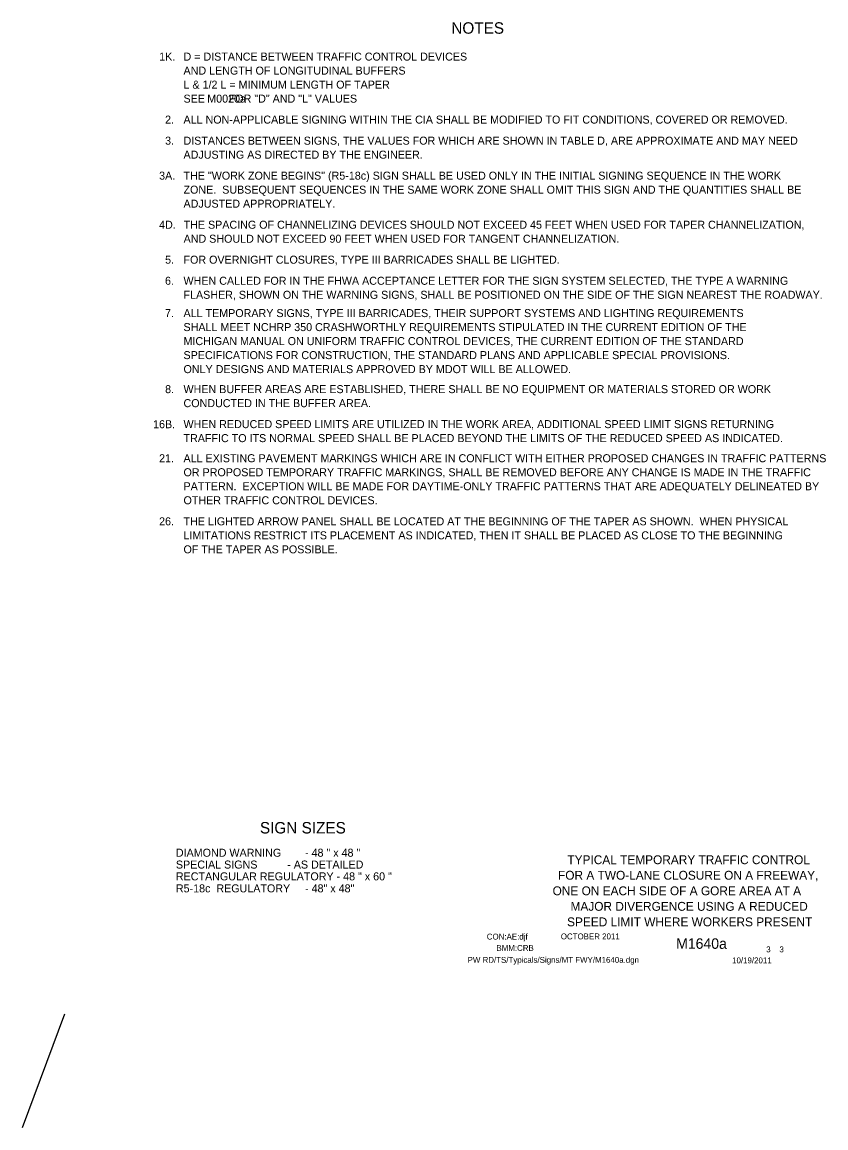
# Model space of a CAD drawing. Extents: x 16512 to 19504, y 5761 to 6984.
# Drawn here: x 18661 to 19504, y 5761 to 6921 of the extents above; entities that cross this region are included whole.
import ezdxf

# ---------------------------------------------------------------- set-up
doc = ezdxf.new("R2010")
doc.units = 0
for name, color, linetype in [('BORDER', 7, 'Continuous'), ('BORDER_SIGNAL_WO', 7, 'Continuous'), ('TYPICAL_TEXT_DIMEN_PR', 7, 'Continuous')]:
    doc.layers.add(name, color=color, linetype=linetype)

msp = doc.modelspace()

# ---------------------------------------------------------------- linework, layer by layer
at = {"layer": 'TYPICAL_TEXT_DIMEN_PR'}
msp.add_line((18705.8, 5880), (18661.5, 5760.5), dxfattribs=at)

# ---------------------------------------------------------------- texts
at = {"layer": 'BORDER'}
for s, p in [('TYPICAL TEMPORARY TRAFFIC CONTROL', (19233.2, 6037.2)), ('FOR A TWO-LANE CLOSURE ON A FREEWAY,', (19223.4, 6020.9)), ('ONE ON EACH SIDE OF A GORE AREA AT A ', (19217.7, 6004.6)), ('MAJOR DIVERGENCE USING A REDUCED', (19236.5, 5988.3)), ('SPEED LIMIT WHERE WORKERS PRESENT', (19232.9, 5972))]:
    msp.add_text(s, height=9.3, dxfattribs=at).set_placement(p)
at = {"layer": 'BORDER_SIGNAL_WO'}
for s, height, p in [('CON:AE:djf  ', 6.2, (19148.7, 5958.1)), ('    OCTOBER 2011    ', 6.2, (19217.1, 5958.3)), ('BMM:CRB   ', 6.2, (19158.8, 5946.2)), ('    M1640a   ', 11, (19330.9, 5948.4)), ('PW RD/TS/Typicals/Signs/MT FWY/M1640a.dgn      ', 6.2, (19128.6, 5933.7)), (' 3    3 ', 6.2, (19439.4, 5944.7)), ('10/19/2011    ', 6.2, (19405.9, 5933.1))]:
    msp.add_text(s, height=height, dxfattribs=at).set_placement(p)
at = {"layer": 'TYPICAL_TEXT_DIMEN_PR'}
for s, height, p in [('NOTES', 12, (19111.5, 6908.5)), ('1K.', 8.4, (18805.2, 6880.3)), ('D = DISTANCE BETWEEN TRAFFIC CONTROL DEVICES', 8.4, (18830.7, 6880.3)), ('AND LENGTH OF LONGITUDINAL BUFFERS', 8.4, (18830.7, 6865.6)), ('L & 1/2 L = MINIMUM LENGTH OF TAPER', 8.4, (18830.7, 6850.9)), ('SEE        FOR "D" AND "L" VALUES', 8.4, (18830.7, 6836.2)), ('M0020a', 8.4, (18855.6, 6836.2)), ('2.', 8.4, (18811.4, 6814.2)), ('ALL NON-APPLICABLE SIGNING WITHIN THE CIA SHALL BE MODIFIED TO FIT CONDITIONS, COVERED OR REMOVED.', 8.4, (18830.7, 6814.2)), ('3.', 8.4, (18811.4, 6792.1)), ('DISTANCES BETWEEN SIGNS, THE VALUES FOR WHICH ARE SHOWN IN TABLE D, ARE APPROXIMATE AND MAY NEED', 8.4, (18830.7, 6792.1)), ('ADJUSTING AS DIRECTED BY THE ENGINEER.', 8.4, (18830.7, 6777.4)), ('3A.', 8.4, (18805.1, 6755.4)), ('THE "WORK ZONE BEGINS" (R5-18c) SIGN SHALL BE USED ONLY IN THE INITIAL SIGNING SEQUENCE IN THE WORK', 8.4, (18830.7, 6755.4)), ('ZONE.  SUBSEQUENT SEQUENCES IN THE SAME WORK ZONE SHALL OMIT THIS SIGN AND THE QUANTITIES SHALL BE', 8.4, (18830.7, 6740.7)), ('ADJUSTED APPROPRIATELY.', 8.4, (18830.7, 6726)), ('4D.', 8.4, (18805.1, 6703.9)), ('THE SPACING OF CHANNELIZING DEVICES SHOULD NOT EXCEED 45 FEET WHEN USED FOR TAPER CHANNELIZATION,', 8.4, (18830.8, 6703.9)), ('AND SHOULD NOT EXCEED 90 FEET WHEN USED FOR TANGENT CHANNELIZATION.', 8.4, (18830.8, 6689.2)), ('5.', 8.4, (18811.4, 6667.2)), ('FOR OVERNIGHT CLOSURES, TYPE III BARRICADES SHALL BE LIGHTED.', 8.4, (18830.7, 6667.2)), ('6.', 8.4, (18811.3, 6645.1)), ('WHEN CALLED FOR IN THE FHWA ACCEPTANCE LETTER FOR THE SIGN SYSTEM SELECTED, THE TYPE A WARNING ', 8.4, (18830.7, 6645.1)), ('FLASHER, SHOWN ON THE WARNING SIGNS, SHALL BE POSITIONED ON THE SIDE OF THE SIGN NEAREST THE ROADWAY.', 8.4, (18830.7, 6630.4)), ('7.', 8.4, (18811.3, 6611.2)), ('ALL TEMPORARY SIGNS, TYPE III BARRICADES, THEIR SUPPORT SYSTEMS AND LIGHTING REQUIREMENTS', 8.4, (18830.7, 6611.2)), ('SHALL MEET NCHRP 350 CRASHWORTHLY REQUIREMENTS STIPULATED IN THE CURRENT EDITION OF THE', 8.4, (18830.7, 6596.5)), ('MICHIGAN MANUAL ON UNIFORM TRAFFIC CONTROL DEVICES, THE CURRENT EDITION OF THE STANDARD', 8.4, (18830.7, 6581.8)), ('SPECIFICATIONS FOR CONSTRUCTION, THE STANDARD PLANS AND APPLICABLE SPECIAL PROVISIONS.', 8.4, (18830.7, 6567.1)), ('ONLY DESIGNS AND MATERIALS APPROVED BY MDOT WILL BE ALLOWED.', 8.4, (18830.7, 6552.4)), ('8.', 8.4, (18811.4, 6531.4)), ('WHEN BUFFER AREAS ARE ESTABLISHED, THERE SHALL BE NO EQUIPMENT OR MATERIALS STORED OR WORK     ', 8.4, (18830.7, 6531.4)), ('CONDUCTED IN THE BUFFER AREA.', 8.4, (18830.7, 6516.7)), ('16B.', 8.4, (18798.8, 6494.6)), ('WHEN REDUCED SPEED LIMITS ARE UTILIZED IN THE WORK AREA, ADDITIONAL SPEED LIMIT SIGNS RETURNING', 8.4, (18830.7, 6494.7)), ('TRAFFIC TO ITS NORMAL SPEED SHALL BE PLACED BEYOND THE LIMITS OF THE REDUCED SPEED AS INDICATED.', 8.4, (18830.7, 6480)), ('21.', 8.4, (18805.1, 6458.9)), ('ALL EXISTING PAVEMENT MARKINGS WHICH ARE IN CONFLICT WITH EITHER PROPOSED CHANGES IN TRAFFIC PATTERNS', 8.4, (18830.7, 6458.9)), ('OR PROPOSED TEMPORARY TRAFFIC MARKINGS, SHALL BE REMOVED BEFORE ANY CHANGE IS MADE IN THE TRAFFIC', 8.4, (18830.7, 6444.2)), ('PATTERN.  EXCEPTION WILL BE MADE FOR DAYTIME-ONLY TRAFFIC PATTERNS THAT ARE ADEQUATELY DELINEATED BY', 8.4, (18830.7, 6429.5)), ('OTHER TRAFFIC CONTROL DEVICES.', 8.4, (18830.7, 6414.8)), ('26.', 8.4, (18805.1, 6392.7)), ('THE LIGHTED ARROW PANEL SHALL BE LOCATED AT THE BEGINNING OF THE TAPER AS SHOWN.  WHEN PHYSICAL', 8.4, (18830.7, 6392.7)), ('LIMITATIONS RESTRICT ITS PLACEMENT AS INDICATED, THEN IT SHALL BE PLACED AS CLOSE TO THE BEGINNING', 8.4, (18830.7, 6378)), ('OF THE TAPER AS POSSIBLE.', 8.4, (18830.7, 6363.3)), ('SIGN SIZES', 12, (18910.8, 6069.4)), ('DIAMOND WARNING        - 48 " x 48 "', 8.4, (18822.7, 6045)), ('SPECIAL SIGNS          - AS DETAILED', 8.4, (18822.7, 6032.6)), ('RECTANGULAR REGULATORY - 48 " x 60 "', 8.4, (18822.7, 6020.2)), ('R5-18c  REGULATORY     - 48" x 48"', 8.4, (18822.7, 6007.6))]:
    msp.add_text(s, height=height, dxfattribs=at).set_placement(p)

doc.saveas('drawing.dxf')
